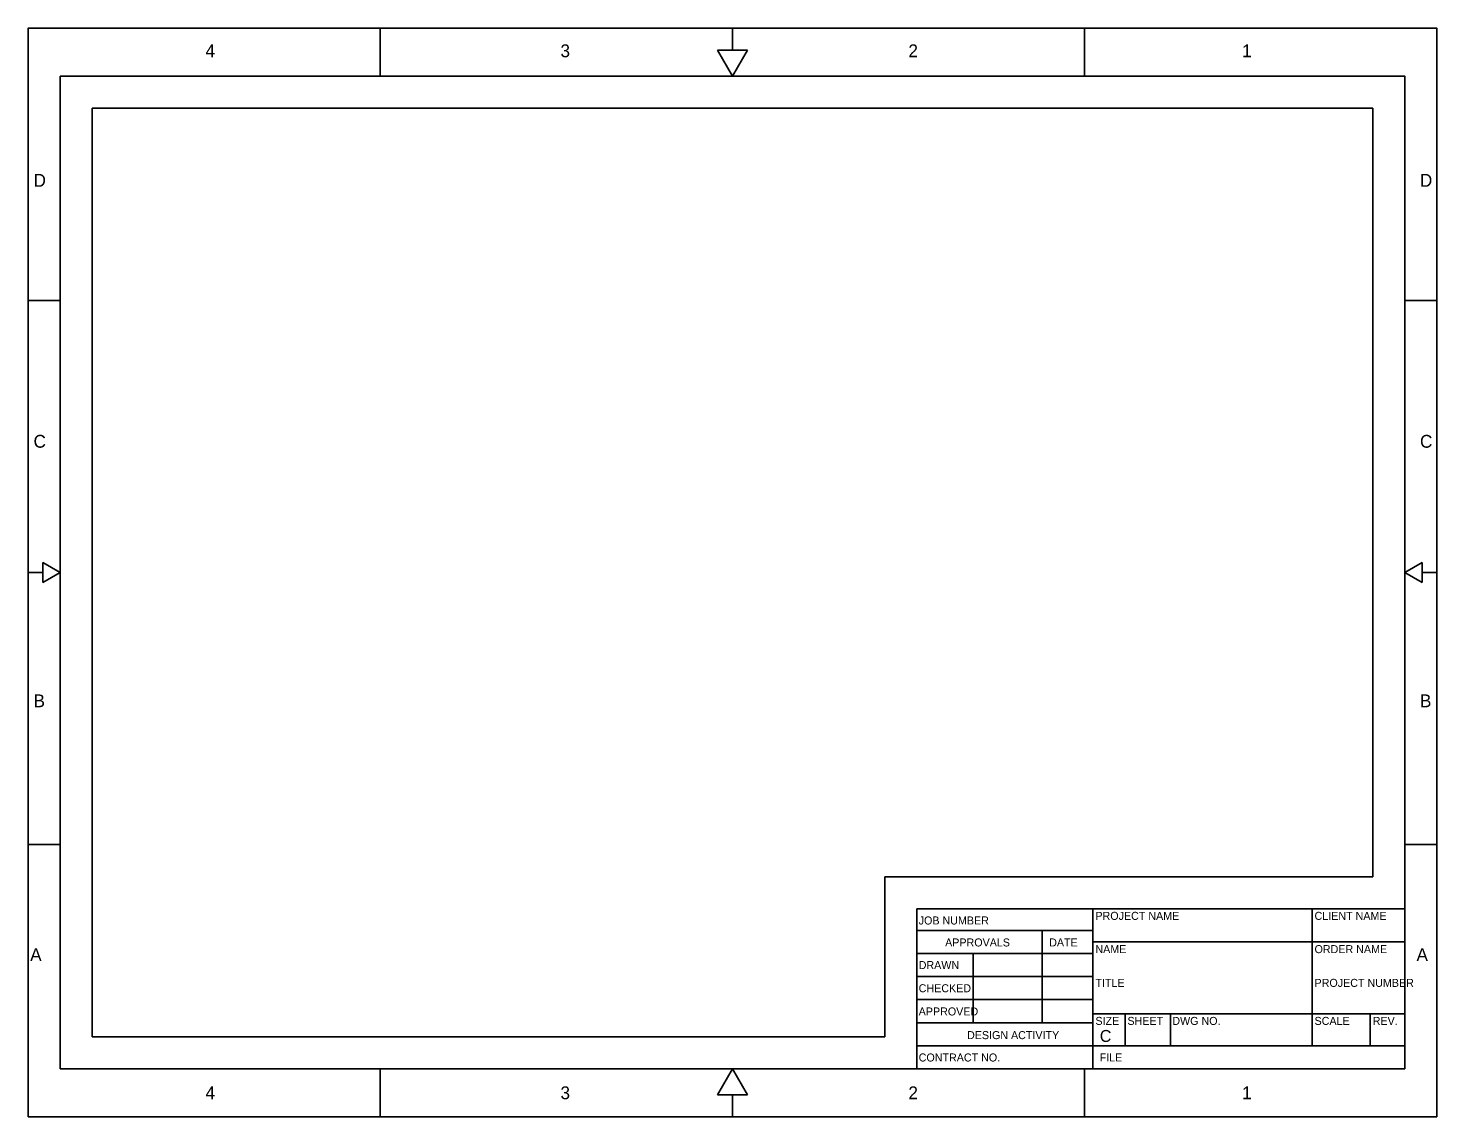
# Model space of a CAD drawing. Extents: x 0 to 1.83, y 0 to 1.42.
import ezdxf

# ---------------------------------------------------------------- set-up
doc = ezdxf.new("R2010")
doc.units = 0
for name, color, linetype in [('Border_outline', 7, 'Continuous'), ('BorderPlot', 7, 'Continuous'), ('ClipShape', 7, 'Continuous'), ('TitleBlock', 7, 'Continuous'), ('TitleBlockText', 7, 'Continuous')]:
    doc.layers.add(name, color=color, linetype=linetype)

# ---------------------------------------------------------------- blocks, each defined once
blk = doc.blocks.new('DC-ANSI-C')
at = {"layer": 'Border_outline'}
for p, q in [((0.4583, 1.4167), (0.4583, 1.3542)), ((0.9167, 1.3881), (0.9167, 1.4167)), ((1.375, 1.4167), (1.375, 1.3542)), ((0.9167, 1.3542), (0.8971, 1.3881)), ((0.8971, 1.3881), (0.9362, 1.3881)), ((0.9167, 1.3542), (0.9362, 1.3881)), ((0.0417, 1.0625), (0, 1.0625)), ((1.7917, 1.0625), (1.8333, 1.0625)), ((0.0417, 0.7083), (0.0191, 0.7214)), ((0.0191, 0.7214), (0.0191, 0.6953)), ((1.7917, 0.7083), (1.8143, 0.7214)), ((1.8143, 0.7214), (1.8143, 0.6953)), ((0.0191, 0.7083), (0, 0.7083)), ((0.0191, 0.6953), (0.0417, 0.7083)), ((1.8143, 0.6953), (1.7917, 0.7083)), ((1.8143, 0.7083), (1.8333, 0.7083)), ((0.0417, 0.3542), (0, 0.3542)), ((1.7917, 0.3542), (1.8333, 0.3542)), ((0.4583, 0), (0.4583, 0.0625)), ((0.9167, 0.0625), (0.8971, 0.0286)), ((0.9167, 0.0625), (0.9362, 0.0286)), ((1.375, 0), (1.375, 0.0625)), ((0.8971, 0.0286), (0.9362, 0.0286)), ((0.9167, 0.0286), (0.9167, 0))]:
    blk.add_line(p, q, dxfattribs=at)
blk.add_lwpolyline([(1.7917, 0.0625), (0.0417, 0.0625), (0.0417, 1.3542), (1.7917, 1.3542)], close=True, dxfattribs=at)
at = {"layer": 'BorderPlot'}
blk.add_lwpolyline([(0, 0), (1.8333, 0), (1.8333, 1.4167), (0, 1.4167)], close=True, dxfattribs=at)
at = {"layer": 'ClipShape'}
for p, q in [((1.75, 1.3125), (0.0833, 1.3125)), ((0.0833, 1.3125), (0.0833, 0.1042)), ((1.75, 0.3125), (1.75, 1.3125)), ((1.115, 0.1042), (1.115, 0.3125)), ((1.115, 0.3125), (1.75, 0.3125)), ((0.0833, 0.1042), (1.115, 0.1042))]:
    blk.add_line(p, q, dxfattribs=at)
at = {"layer": 'TitleBlock'}
for p, q in [((1.1567, 0.0625), (1.1567, 0.2708)), ((1.1567, 0.2708), (1.7917, 0.2708)), ((1.3858, 0.0625), (1.3858, 0.2708)), ((1.671, 0.0925), (1.671, 0.2708)), ((1.1567, 0.2425), (1.3858, 0.2425)), ((1.3199, 0.1225), (1.3199, 0.2425)), ((1.3858, 0.2275), (1.7917, 0.2275)), ((1.1567, 0.2125), (1.3858, 0.2125)), ((1.23, 0.1225), (1.23, 0.2125)), ((1.1567, 0.1825), (1.3858, 0.1825)), ((1.1567, 0.1525), (1.3858, 0.1525)), ((1.3858, 0.1342), (1.7917, 0.1342)), ((1.4275, 0.0925), (1.4275, 0.1342)), ((1.4868, 0.0925), (1.4868, 0.1342)), ((1.7465, 0.0925), (1.7465, 0.1342)), ((1.1567, 0.1225), (1.3858, 0.1225)), ((1.1567, 0.0925), (1.7917, 0.0925)), ((1.7917, 0.0625), (1.7917, 0.0625))]:
    blk.add_line(p, q, dxfattribs=at)
at = {"layer": 'Border_outline'}
for s, p in [('4', (0.2308, 1.3789)), ('3', (0.6928, 1.3789)), ('2', (1.1456, 1.3789)), ('1', (1.58, 1.3789)), ('D', (0.007, 1.2103)), ('D', (1.8113, 1.2103)), ('C', (0.007, 0.8707)), ('C', (1.8114, 0.8707)), ('B', (0.007, 0.533)), ('B', (1.8114, 0.533)), ('A', (0.0026, 0.2027)), ('A', (1.8069, 0.2027)), ('4', (0.2308, 0.0229)), ('3', (0.6928, 0.0229)), ('2', (1.1456, 0.0229)), ('1', (1.58, 0.0229))]:
    blk.add_text(s, height=0.0167, dxfattribs=at).set_placement(p)
at = {"layer": 'TitleBlock'}
blk.add_text('C', height=0.0156, dxfattribs=at).set_placement((1.3947, 0.0974))
at = {"layer": 'TitleBlockText'}
for s, height, p in [('JOB NUMBER', 0.01042, (1.159, 0.2503)), ('PROJECT NAME', 0.010417, (1.389, 0.2563)), ('CLIENT NAME', 0.010417, (1.6742, 0.2563)), ('APPROVALS', 0.01042, (1.1934, 0.2217)), ('DATE', 0.01042, (1.3288, 0.2217)), ('NAME', 0.01042, (1.389, 0.213)), ('ORDER NAME', 0.01042, (1.6742, 0.213)), ('DRAWN', 0.01042, (1.159, 0.1923)), ('CHECKED', 0.01042, (1.159, 0.1621)), ('TITLE', 0.01042, (1.389, 0.1691)), ('PROJECT NUMBER', 0.010417, (1.6742, 0.1691)), ('APPROVED', 0.01042, (1.159, 0.1319)), ('SIZE', 0.01042, (1.389, 0.1196)), ('SHEET', 0.01042, (1.4307, 0.1196)), ('DWG NO.', 0.01042, (1.4891, 0.1196)), ('SCALE', 0.01042, (1.6742, 0.1196)), ('REV.', 0.01042, (1.7499, 0.1196)), ('DESIGN ACTIVITY', 0.010417, (1.2219, 0.1011)), ('CONTRACT NO.', 0.010417, (1.159, 0.072)), ('FILE', 0.01042, (1.3945, 0.0721))]:
    blk.add_text(s, height=height, dxfattribs=at).set_placement(p)

msp = doc.modelspace()

# ---------------------------------------------------------------- block references
msp.add_blockref('DC-ANSI-C', (0, 0))

doc.saveas('drawing.dxf')
